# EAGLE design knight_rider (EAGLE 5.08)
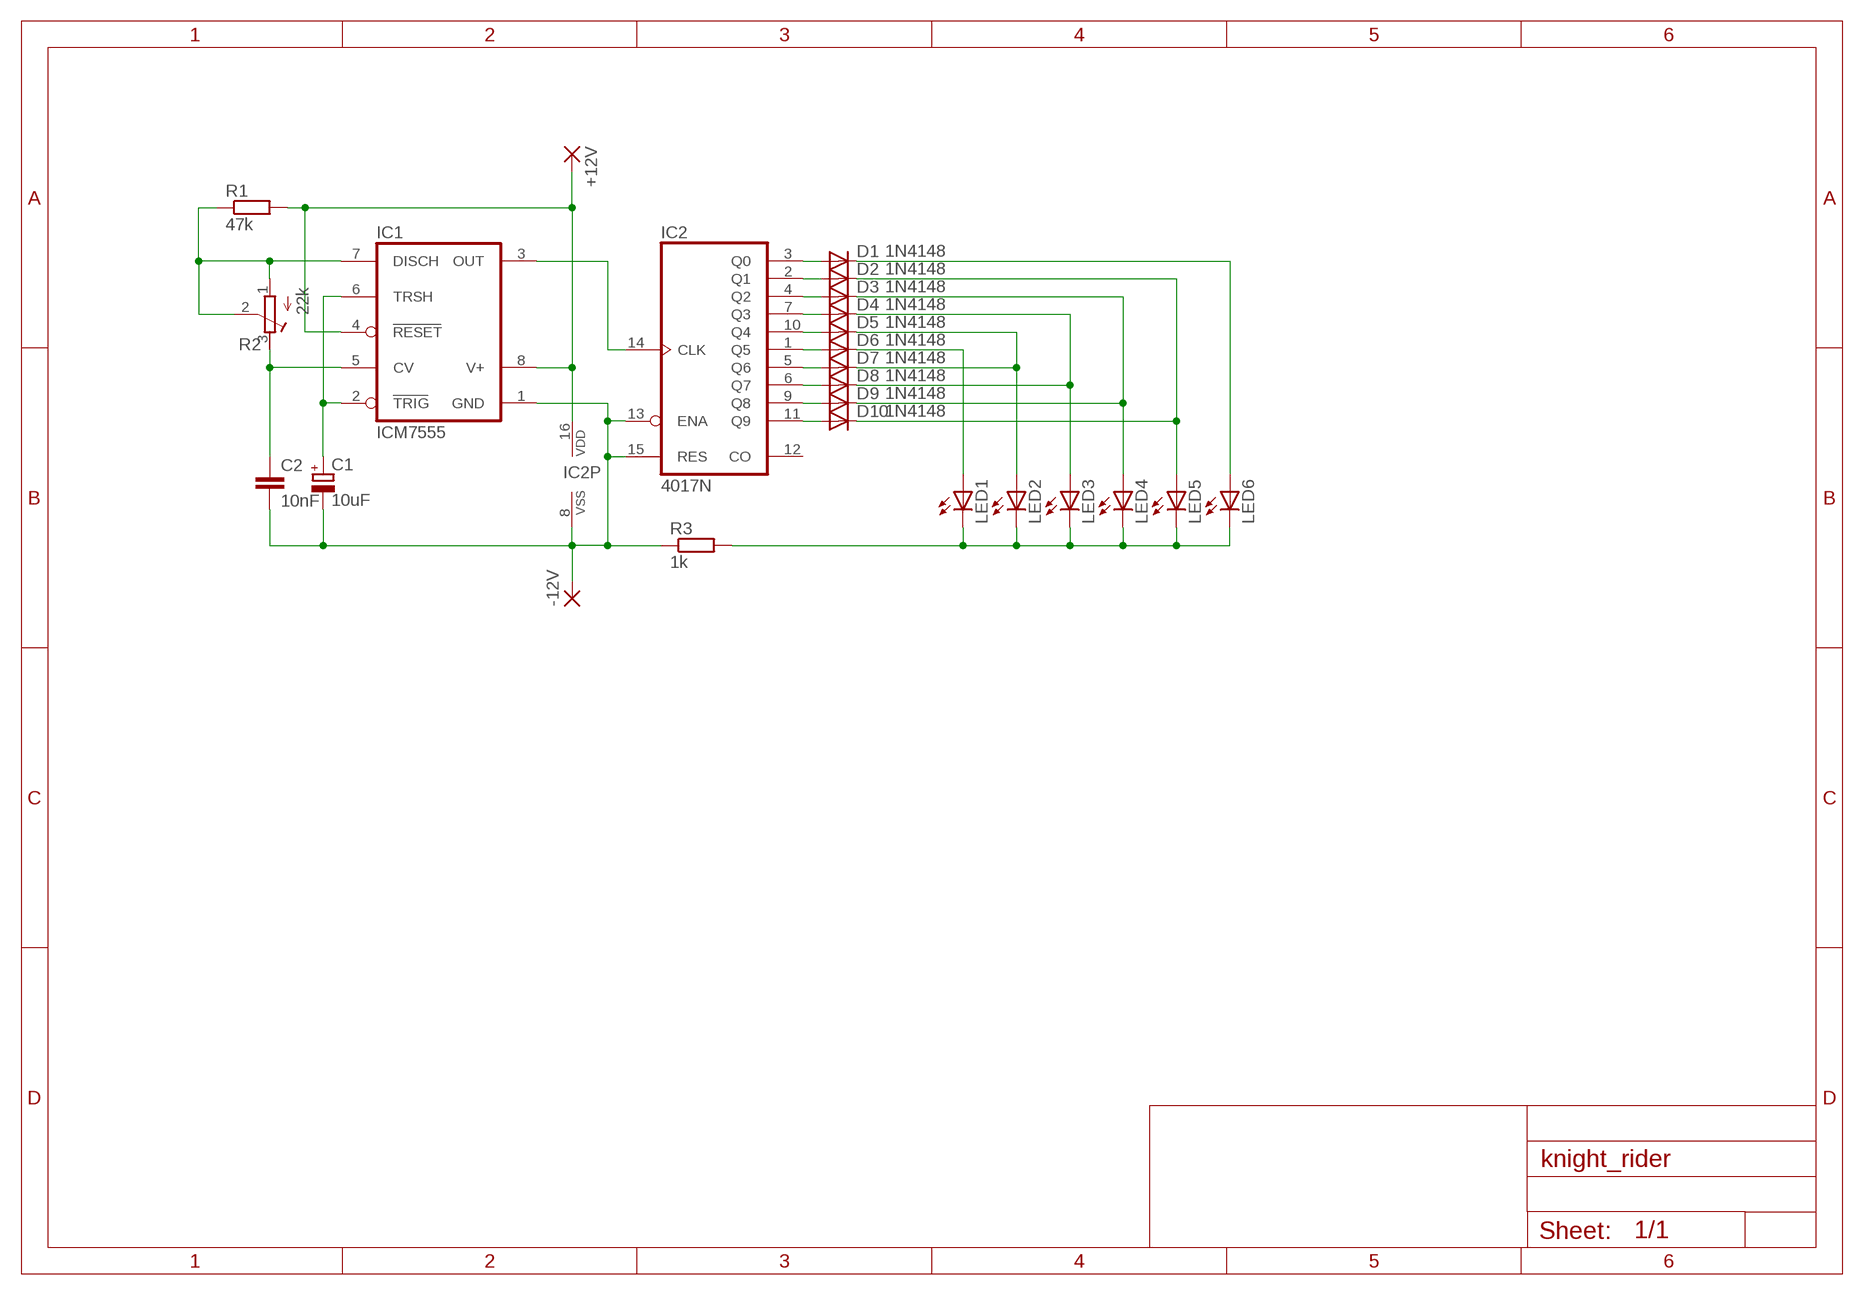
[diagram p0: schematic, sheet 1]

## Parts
+12V  2,54/1,0  [2,54/1,0]
-12V  2,54/1,0  [2,54/1,0]
C1  10uF  CPOL-EUE2.5-5  [E2,5-5]
C2  10nF  C-EU050-025X075  [C050-025X075]
D1  1N4148  1N4148DO35-7  [DO35-7]
D2  1N4148  1N4148DO35-7  [DO35-7]
D3  1N4148  1N4148DO35-7  [DO35-7]
D4  1N4148  1N4148DO35-7  [DO35-7]
D5  1N4148  1N4148DO35-7  [DO35-7]
D6  1N4148  1N4148DO35-7  [DO35-7]
D7  1N4148  1N4148DO35-7  [DO35-7]
D8  1N4148  1N4148DO35-7  [DO35-7]
D9  1N4148  1N4148DO35-7  [DO35-7]
D10  1N4148  1N4148DO35-7  [DO35-7]
IC1  ICM7555  [DIL08]
IC2  4017N  [DIL16]
LED1  LED5MM  [LED5MM]
LED2  LED5MM  [LED5MM]
LED3  LED5MM  [LED5MM]
LED4  LED5MM  [LED5MM]
LED5  LED5MM  [LED5MM]
LED6  LED5MM  [LED5MM]
R1  47k  R-EU_0207/10  [0207/10]
R2  22k  R-TRIMM3339P  [RTRIM3339P]
R3  1k  R-EU_0207/10  [0207/10]

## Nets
N$1 [Sygnal]: IC1.3(OUT) IC2.14(CLK)
N$2 [Zasilanie]: -12V.1(P) C1.- C2.2 IC1.1(GND) IC2.8(VSS) IC2.13(ENA) IC2.15(RES) R3.1
N$3 [Zasilanie]: +12V.1(P) IC1.4(RESET) IC1.8(V+) IC2.16(VDD) R1.2
N$4 [Zasilanie]: C1.+ IC1.2(TRIG) IC1.6(TRSH)
N$5 [Sygnal]: D1.A IC2.3(Q0)
N$6 [Sygnal]: D2.A IC2.2(Q1)
N$7 [Sygnal]: C2.1 IC1.5(CV) R2.3(A)
N$8 [Sygnal]: IC1.7(DISCH) R1.1 R2.1(E) R2.2(S)
N$9 [Sygnal]: D3.A IC2.4(Q2)
N$10 [Sygnal]: D4.A IC2.7(Q3)
N$11 [Sygnal]: D5.A IC2.10(Q4)
N$12 [Sygnal]: D6.A IC2.1(Q5)
N$13 [Sygnal]: D7.A IC2.5(Q6)
N$14 [Sygnal]: D8.A IC2.6(Q7)
N$15 [Sygnal]: D9.A IC2.9(Q8)
N$16 [Sygnal]: D10.A IC2.11(Q9)
N$17 [Zasilanie]: D1.C LED6.A
N$18 [Zasilanie]: D2.C D10.C LED5.A
N$19 [Zasilanie]: D3.C D9.C LED4.A
N$20 [Zasilanie]: D4.C D8.C LED3.A
N$21 [Zasilanie]: D5.C D7.C LED2.A
N$22 [Zasilanie]: D6.C LED1.A
N$23 [Zasilanie]: LED1.K(C) LED2.K(C) LED3.K(C) LED4.K(C) LED5.K(C) LED6.K(C) R3.2
Unconnected: IC2.12(CO)

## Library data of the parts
+12V -12V = wirepad:2,54/1,0: THROUGH-HOLE PAD
C1 = rcl:CPOL-EU: POLARIZED CAPACITOR, European symbol
C2 = rcl:C-EU: CAPACITOR, European symbol
D1-D10 = diode:1N4148: DIODE
IC1 = maxim:ICM7555: TIMER
IC2 = 40xx:4017: COUNTER/DIVIDER
LED1-LED6 = led:LED: LED
R1 R3 = rcl:R-EU_: RESISTOR, European symbol
R2 = rcl:R-TRIMM: Trimm resistor

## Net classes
1 Sygnal: width 0.762 mm
2 Zasilanie: width 1.016 mm

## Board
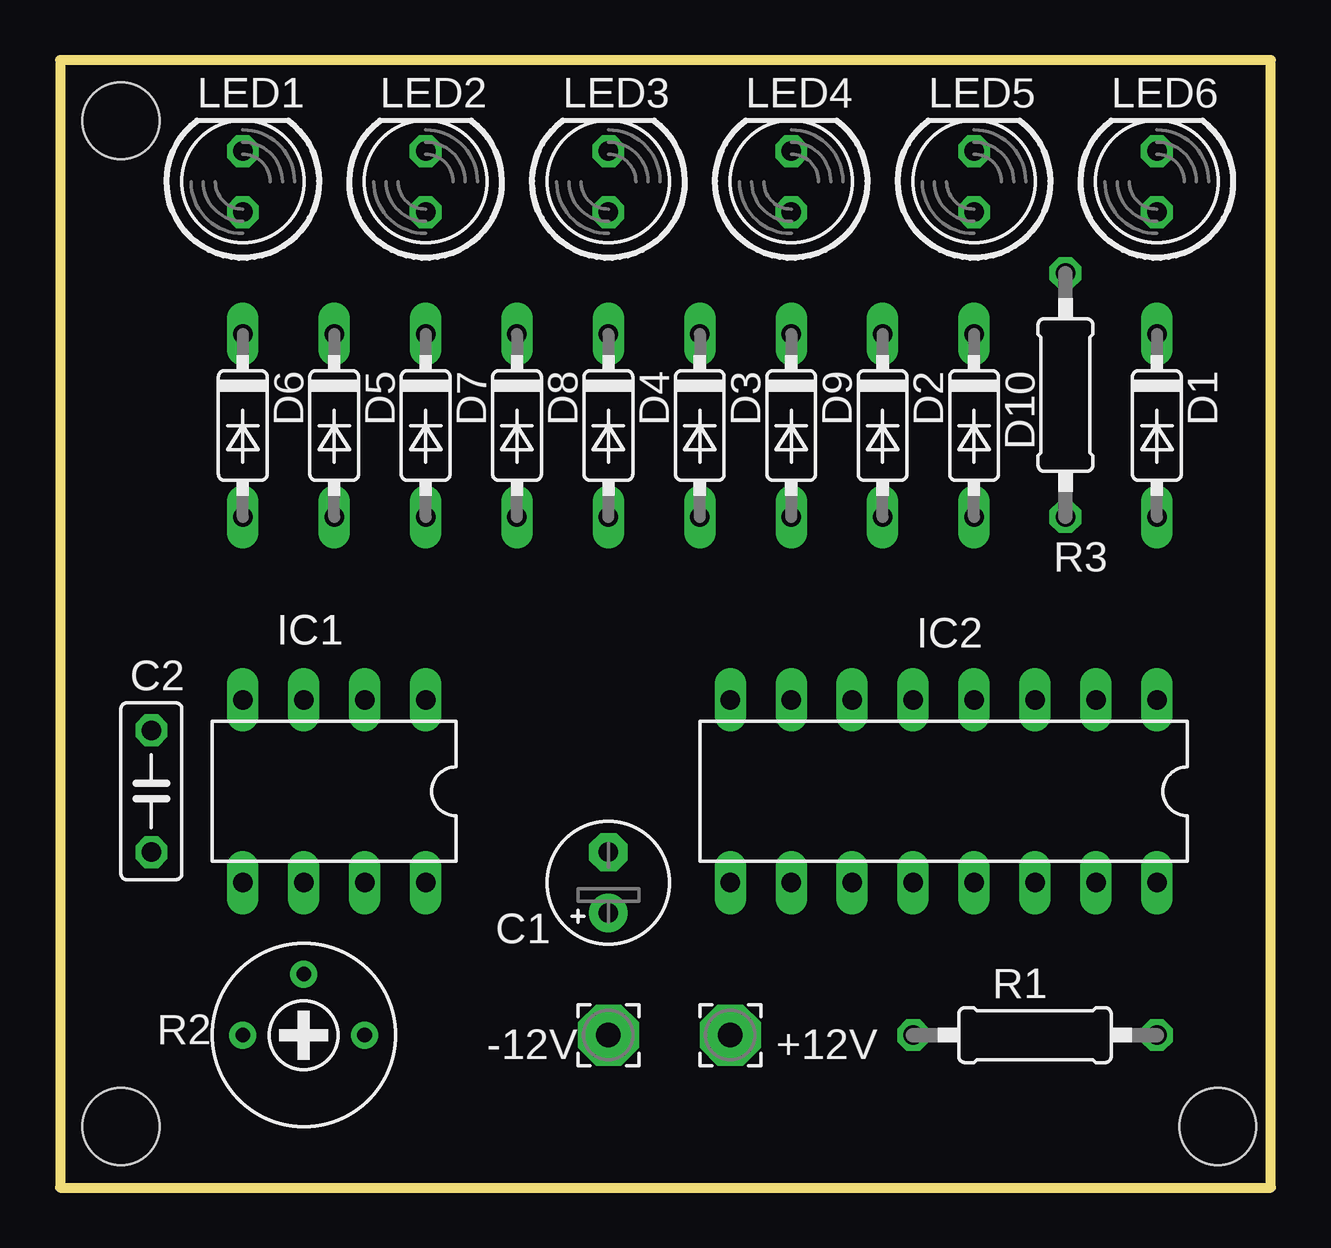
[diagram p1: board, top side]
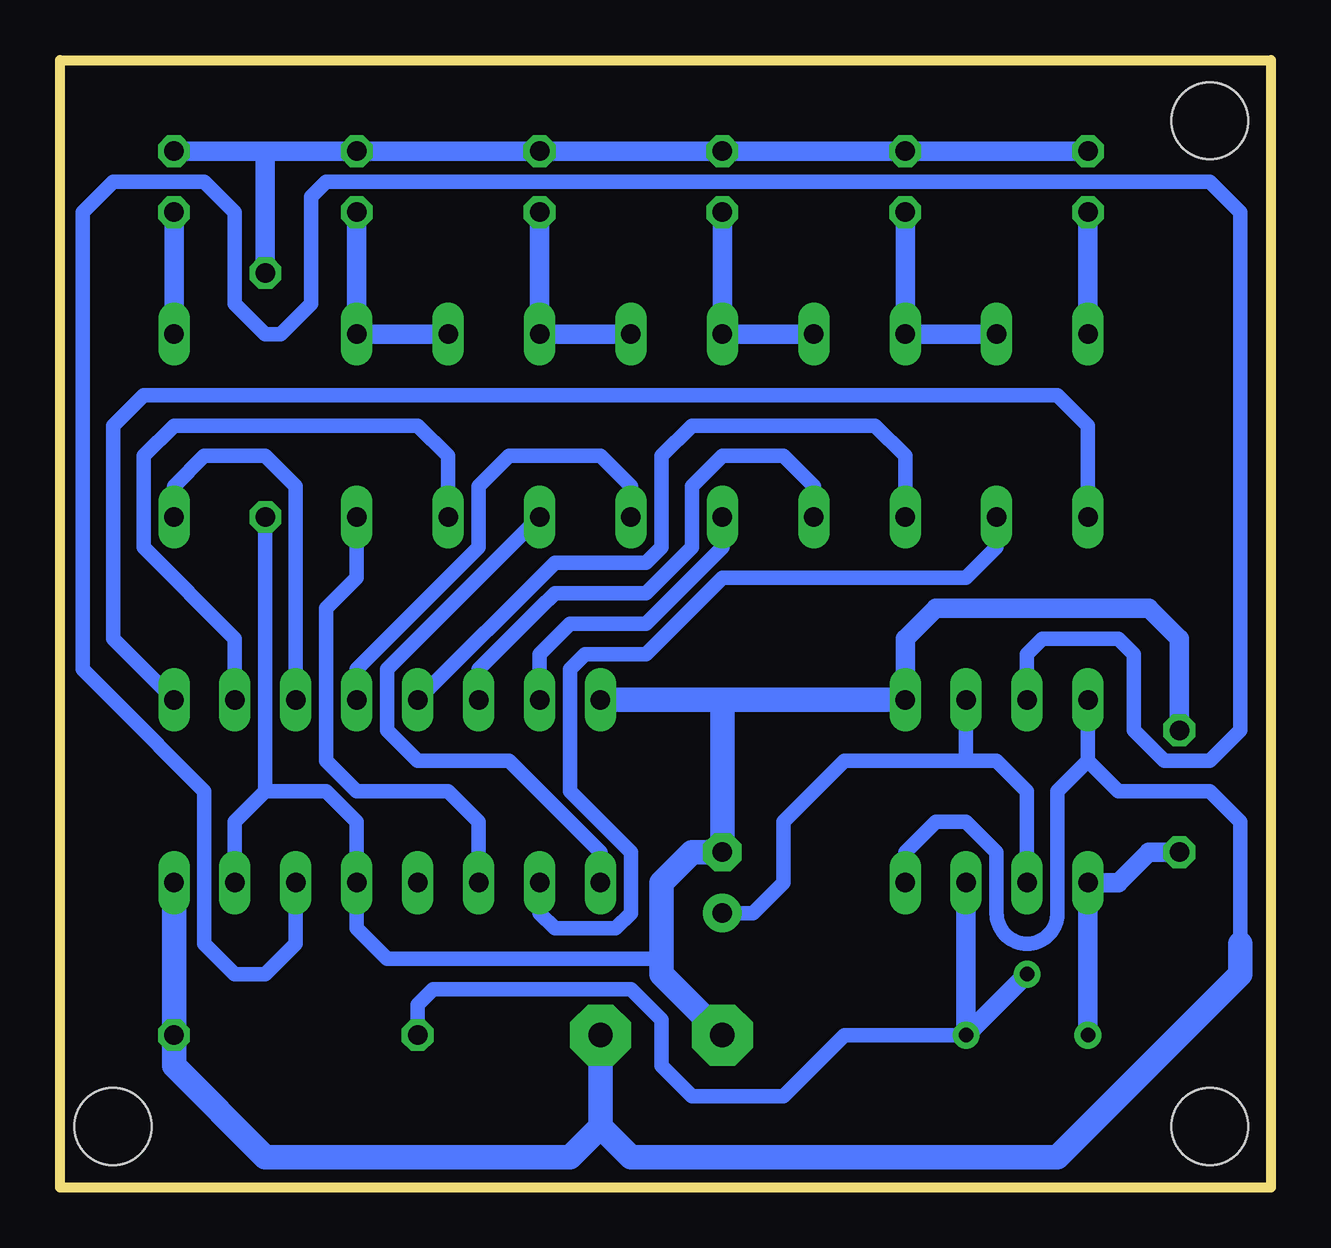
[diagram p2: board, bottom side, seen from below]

Size 50.47 x 46.98 mm. Coordinates in mm from the lower left corner, seen from the top.
Outline: 0,0 50.47,0 50.47,46.98 0,46.98 0,0
Copper layers (1*16): Top 0.035mm / dielectric 1.5mm / Bottom 0.035mm
Design rules "default": minimum track width 10mil, minimum drill 24mil, track to track 8mil, track to pad 8mil, pad to pad 8mil, via to via 8mil, smd to smd 8mil, copper to edge 40mil, drill to drill 8mil, minimum pad ring 10mil, minimum via ring 8mil, stop-mask expansion 4mil, vias tented up to drill 0mil, thermal gap 10mil
Holes 3.2 mm at 2.54,44.45 48.26,2.54 2.54,2.54

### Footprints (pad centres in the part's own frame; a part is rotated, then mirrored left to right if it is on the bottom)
2,54/1,0 = drill 1.016 pad 2.54 octagon: 1 0,0
E2,5-5 = drill 0.813 pad 1.6 round: + -1.27,0 | drill 0.813 pad 1.6 octagon: - 1.27,0
C050-025X075 = drill 0.813 octagon: 1 -2.54,0; 2 2.54,0
DO35-7 = drill 0.813 long: A 3.81,0; C -3.81,0
DIL08 = drill 0.813 long: 1 -3.81,-3.81; 2 -1.27,-3.81; 3 1.27,-3.81; 4 3.81,-3.81; 5 3.81,3.81; 6 1.27,3.81; 7 -1.27,3.81; 8 -3.81,3.81
DIL16 = drill 0.813 long: 1 -8.89,-3.81; 2 -6.35,-3.81; 3 -3.81,-3.81; 4 -1.27,-3.81; 5 1.27,-3.81; 6 3.81,-3.81; 7 6.35,-3.81; 8 8.89,-3.81; 9 8.89,3.81; 10 6.35,3.81; 11 3.81,3.81; 12 1.27,3.81; 13 -1.27,3.81; 14 -3.81,3.81; 15 -6.35,3.81; 16 -8.89,3.81
LED5MM = drill 0.813 octagon: A -1.27,0; K 1.27,0
0207/10 = drill 0.813 octagon: 1 -5.08,0; 2 5.08,0
RTRIM3339P = drill 0.61 round: 1 -2.54,0; 2 0,-2.54; 3 2.54,0

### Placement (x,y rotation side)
+12V  27.94,6.35 0 top
-12V  22.86,6.35 0 top
C1  22.86,12.7 90 top
C2  3.81,16.51 90 top
D1  45.72,31.75 270 top
D2  34.29,31.75 270 top
D3  26.67,31.75 270 top
D4  22.86,31.75 270 top
D5  11.43,31.75 270 top
D6  7.62,31.75 270 top
D7  15.24,31.75 270 top
D8  19.05,31.75 270 top
D9  30.48,31.75 270 top
D10  38.1,31.75 270 top
IC1  11.43,16.51 180 top
IC2  36.83,16.51 180 top
LED1  7.62,41.91 90 top
LED2  15.24,41.91 90 top
LED3  22.86,41.91 90 top
LED4  30.48,41.91 90 top
LED5  38.1,41.91 90 top
LED6  45.72,41.91 90 top
R1  40.64,6.35 0 top
R2  10.16,6.35 180 top
R3  41.91,33.02 90 top

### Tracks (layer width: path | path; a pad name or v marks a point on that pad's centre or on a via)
N$1
  Bottom 0.61: IC2.14 40.64,10.16 41.91,8.89 43.18,8.89 44.45,10.16 44.45,16.51 48.26,20.32 49.53,21.59 49.53,38.1 49.53,40.64 48.26,41.91 44.45,41.91 43.18,40.64 43.18,36.83 41.91,35.56 41.27,35.56 40.01,36.83 40.01,41.27 39.37,41.91 2.54,41.91 1.27,40.64 1.27,19.05 2.54,17.78 4.45,17.78 5.71,19.05 5.71,22.23 6.35,22.86 9.53,22.86 10.16,22.23 IC1.3
N$2
  Bottom 0.61: 41.91,16.51 R3.1 | 41.91,16.51 43.18,15.24 IC2.15 | 38.1,15.24 IC2.13 | 38.1,15.24 39.37,16.51 41.91,16.51 | 38.1,15.24 38.1,10.79 36.83,9.53 25.4,9.53
  Bottom 0.812: C2.2 3.81,21.59 3.81,22.86 5.08,24.13 13.97,24.13 15.24,22.86 IC1.1
  Bottom 1.016: IC1.1 22.86,20.32 | 22.86,20.32 IC2.8 | 22.86,20.32 C1.- 24.13,13.97 25.4,12.7 25.4,9.53 25.4,8.89 -12V.1
N$3
  Bottom 0.61: IC1.8 15.24,13.97 13.97,15.24 12.7,15.24 11.43,13.97 11.43,11.43 arc-90 10.16,10.16 arc-90 8.89,11.43 8.89,16.51 7.62,17.78 | 7.62,17.78 IC1.4 | 1.27,10.16 1.27,15.24 2.54,16.51 6.35,16.51 7.62,17.78
  Bottom 1.016: IC2.16 R1.2 45.72,5.08 41.91,1.27 29.21,1.27 27.94,2.54 | 27.94,2.54 +12V.1 27.94,2.54 | 27.94,2.54 26.67,1.27 8.89,1.27 1.27,8.89 1.27,10.16
N$4
  Bottom 0.61: 12.7,17.78 IC1.2 | IC1.6 10.16,13.97 10.16,16.51 11.43,17.78 12.7,17.78 | C1.+ 21.59,11.43 20.32,12.7 20.32,15.24 19.05,16.51 17.78,17.78 12.7,17.78
N$5
  Bottom 0.61: D1.A 45.72,29.21 44.45,30.48 41.91,30.48 40.64,29.21 IC2.3
N$6
  Bottom 0.61: D2.A 34.29,30.48 35.56,31.75 45.72,31.75 46.99,30.48 46.99,26.67 43.18,22.86 IC2.2
N$7
  Bottom 0.813: R2.3 IC1.5 6.35,12.7 5.08,13.97 C2.1
N$8
  Bottom 0.61: R2.1 17.78,6.35 20.32,3.81 24.13,3.81 25.4,5.08 25.4,6.99 26.67,8.26 34.92,8.26 35.56,7.62 R1.1
  Bottom 0.813: IC1.7 12.7,11.43 R2.1 R2.2
N$9
  Bottom 0.61: D3.A 26.67,29.21 27.94,30.48 31.75,30.48 33.02,29.21 33.02,26.67 35.56,24.13 38.1,21.59 IC2.4
N$10
  Bottom 0.61: D4.A 22.86,26.67 26.04,23.5 29.21,23.5 30.48,22.23 IC2.7
N$11
  Bottom 0.61: D5.A 11.43,26.67 12.7,25.4 20.32,25.4 22.86,25.4 26.04,22.23 28.57,22.23 29.21,21.59 29.21,16.51 26.67,13.97 26.67,11.43 27.3,10.79 29.84,10.79 30.48,11.43 IC2.10
N$12
  Bottom 0.61: D6.A 7.62,31.75 8.89,33.02 46.99,33.02 48.26,31.75 48.26,22.86 IC2.1
N$13
  Bottom 0.61: D7.A 15.24,30.48 16.51,31.75 24.13,31.75 25.4,30.48 25.4,26.67 26.04,26.04 29.84,26.04 IC2.5
N$14
  Bottom 0.61: D8.A 19.05,29.21 20.32,30.48 22.86,30.48 24.13,29.21 24.13,26.67 25.4,25.4 26.04,24.77 29.84,24.77 30.48,24.13 31.75,22.86 33.02,21.59 IC2.6
N$15
  Bottom 0.61: D9.A 36.83,21.59 36.83,19.05 35.56,17.78 31.75,17.78 27.94,13.97 IC2.9
N$16
  Bottom 0.61: D10.A 38.1,25.4 39.37,24.13 39.37,17.78 38.1,16.51 34.29,16.51 33.02,15.24 IC2.11
N$17
  Bottom 0.813: D1.C LED6.A
N$18
  Bottom 0.813: D2.C D10.C LED5.A
N$19
  Bottom 0.813: D3.C D9.C LED4.A
N$20
  Bottom 0.813: D8.C D4.C LED3.A
N$21
  Bottom 0.813: LED2.A D7.C D5.C
N$22
  Bottom 0.813: D6.C LED1.A
N$23
  Bottom 0.813: LED1.K LED2.K LED3.K LED4.K LED5.K 41.91,43.18 | 41.91,43.18 LED6.K | 41.91,43.18 R3.2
